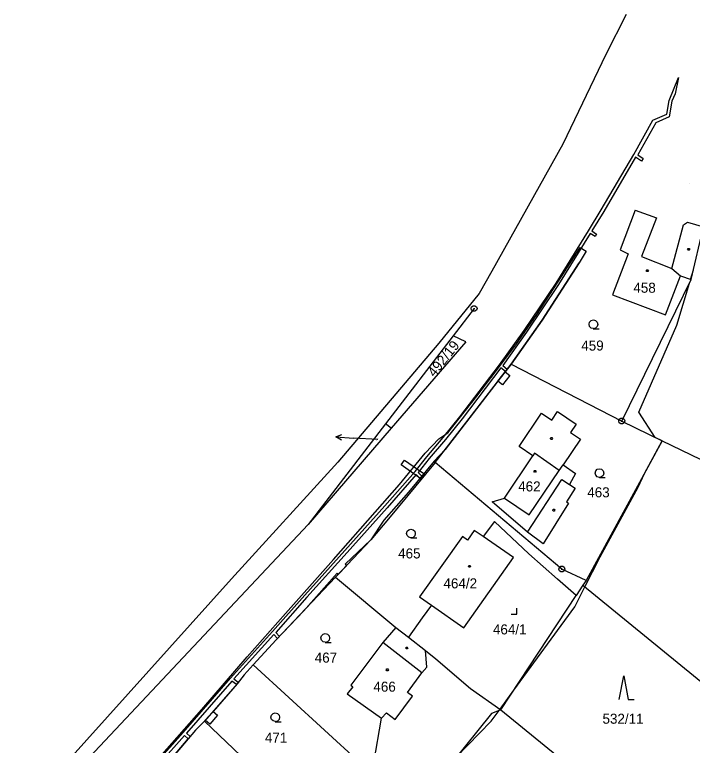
# Model space of a CAD drawing. Extents: x -759699 to -757730, y -1172308 to -1170857.
# Drawn here: x -759460.8 to -759346, y -1171711.2 to -1171587.4 of the extents above; entities that cross this region are included whole.
import ezdxf

# ---------------------------------------------------------------- set-up
doc = ezdxf.new("R2010")
doc.units = 0
for name, color, linetype in [('Vrstva 1', 7, 'Continuous'), ('Vrstva 11', 7, 'Continuous'), ('Vrstva 12', 7, 'Continuous'), ('Vrstva 13', 7, 'Continuous'), ('Vrstva 2', 7, 'Continuous'), ('Vrstva 3', 7, 'Continuous'), ('Vrstva 4', 7, 'Continuous'), ('Vrstva 5', 7, 'Continuous'), ('Vrstva 7', 7, 'Continuous'), ('Vrstva 8', 7, 'Continuous')]:
    doc.layers.add(name, color=color, linetype=linetype)

msp = doc.modelspace()

# ---------------------------------------------------------------- linework, layer by layer
at = {"layer": 'Vrstva 1'}
for p, q in [((-759355.74, -1171620.53), (-759358.28, -1171627.26)), ((-759355.74, -1171620.53), (-759355.74, -1171620.53)), ((-759346.22, -1171632.28), (-759344.12, -1171623.36)), ((-759356.89, -1171627.92), (-759359.55, -1171634.86)), ((-759358.28, -1171627.26), (-759356.89, -1171627.92)), ((-759371.45, -1171639.14), (-759365.18, -1171629.47)), ((-759365.18, -1171629.47), (-759365.18, -1171629.47)), ((-759350.56, -1171638.25), (-759348.04, -1171631.67)), ((-759348.04, -1171631.67), (-759346.22, -1171632.28)), ((-759357.99, -1171656.24), (-759346.22, -1171632.28)), ((-759359.55, -1171634.86), (-759350.56, -1171638.25)), ((-759382.99, -1171637.18), (-759386.53, -1171641.8)), ((-759382.99, -1171637.18), (-759382.99, -1171637.18)), ((-759376.73, -1171646.62), (-759371.45, -1171639.14)), ((-759386.53, -1171641.8), (-759397.96, -1171656.69)), ((-759384.4, -1171642.85), (-759397, -1171657.44)), ((-759384.4, -1171642.85), (-759386.53, -1171641.8)), ((-759384.4, -1171642.85), (-759384.4, -1171642.85)), ((-759389.58, -1171663.24), (-759376.73, -1171646.62)), ((-759376.73, -1171646.62), (-759357.99, -1171656.24)), ((-759375.36, -1171660.56), (-759371.57, -1171654.91)), ((-759371.57, -1171654.91), (-759369.84, -1171656.07)), ((-759369.84, -1171656.07), (-759368.88, -1171654.63)), ((-759368.88, -1171654.63), (-759365.71, -1171656.75)), ((-759357.99, -1171656.24), (-759351.15, -1171659.61)), ((-759397.96, -1171656.69), (-759411.06, -1171673.74)), ((-759397, -1171657.44), (-759411.06, -1171673.74)), ((-759397, -1171657.44), (-759397.96, -1171656.69)), ((-759365.71, -1171656.75), (-759366.68, -1171658.19)), ((-759366.68, -1171658.19), (-759364.99, -1171659.32)), ((-759364.99, -1171659.32), (-759367.9, -1171663.64)), ((-759351.15, -1171659.61), (-759364.03, -1171683.25)), ((-759351.15, -1171659.61), (-759313.61, -1171677.58)), ((-759373.03, -1171662.12), (-759375.36, -1171660.56)), ((-759377.85, -1171669.3), (-759373.03, -1171662.12)), ((-759389.58, -1171663.24), (-759397.5, -1171672.82)), ((-759368.13, -1171681.31), (-759389.58, -1171663.24)), ((-759367.9, -1171663.64), (-759365.84, -1171665.15)), ((-759365.84, -1171665.15), (-759366.86, -1171666.97)), ((-759365.9, -1171667.61), (-759367.36, -1171669.94)), ((-759366.86, -1171666.97), (-759365.9, -1171667.61)), ((-759379.9, -1171669.9), (-759377.85, -1171669.3)), ((-759373.97, -1171675.05), (-759379.9, -1171669.9)), ((-759366.98, -1171670.17), (-759371.29, -1171677.05)), ((-759367.36, -1171669.94), (-759366.98, -1171670.17)), ((-759411.06, -1171673.74), (-759460.06, -1171725.87)), ((-759397.5, -1171672.82), (-759400.48, -1171676.34)), ((-759379.51, -1171673.24), (-759381.45, -1171675.82)), ((-759373.71, -1171678.71), (-759379.51, -1171673.24)), ((-759382.98, -1171674.78), (-759384.11, -1171676.43)), ((-759381.45, -1171675.82), (-759382.98, -1171674.78)), ((-759371.29, -1171677.05), (-759373.97, -1171675.05)), ((-759400.48, -1171676.34), (-759406.46, -1171682.69)), ((-759384.94, -1171675.79), (-759392.24, -1171686.04)), ((-759384.11, -1171676.43), (-759384.94, -1171675.79)), ((-759376.3, -1171679.33), (-759381.45, -1171675.82)), ((-759368.84, -1171683.01), (-759373.71, -1171678.71)), ((-759384.72, -1171691.25), (-759376.3, -1171679.33)), ((-759364.03, -1171683.25), (-759368.13, -1171681.31)), ((-759406.46, -1171682.69), (-759416.48, -1171693.29)), ((-759406.46, -1171682.69), (-759396.24, -1171691.2)), ((-759365.7, -1171685.78), (-759368.84, -1171683.01)), ((-759364.03, -1171683.25), (-759364.55, -1171684.03)), ((-759364.55, -1171684.03), (-759365.7, -1171685.78)), ((-759364.55, -1171684.03), (-759333.09, -1171709.78)), ((-759392.24, -1171686.04), (-759390.2, -1171687.45)), ((-759378.43, -1171705.14), (-759365.7, -1171685.78)), ((-759390.2, -1171687.45), (-759391.8, -1171689.57)), ((-759390.2, -1171687.45), (-759384.72, -1171691.25)), ((-759391.8, -1171689.57), (-759394.11, -1171692.85)), ((-759396.24, -1171691.2), (-759398.45, -1171693.74)), ((-759396.24, -1171691.2), (-759394.11, -1171692.85)), ((-759416.48, -1171693.29), (-759420.41, -1171697.55)), ((-759398.45, -1171693.74), (-759403.86, -1171701)), ((-759394.11, -1171692.85), (-759391.21, -1171695.12)), ((-759391.21, -1171695.12), (-759389.44, -1171696.5)), ((-759389.44, -1171696.5), (-759383.58, -1171701.54)), ((-759420.41, -1171697.55), (-759421.89, -1171699.23)), ((-759420.41, -1171697.55), (-759400.3, -1171715.91)), ((-759421.89, -1171699.23), (-759423.12, -1171700.74)), ((-759423.12, -1171700.74), (-759428.63, -1171707.06)), ((-759403.86, -1171701), (-759403.53, -1171701.26)), ((-759403.53, -1171701.26), (-759404.46, -1171702.46)), ((-759383.58, -1171701.54), (-759378.43, -1171705.14)), ((-759404.46, -1171702.46), (-759398.64, -1171706.59)), ((-759380.05, -1171705.77), (-759393.97, -1171723.12)), ((-759378.43, -1171705.14), (-759380.05, -1171705.77)), ((-759378.43, -1171705.14), (-759347.86, -1171730.08)), ((-759428.63, -1171707.06), (-759430.17, -1171708.62)), ((-759428.63, -1171707.06), (-759414.89, -1171720.1)), ((-759400.3, -1171715.91), (-759398.64, -1171706.59)), ((-759430.17, -1171708.62), (-759431.38, -1171710.06)), ((-759436.98, -1171716.58), (-759431.38, -1171710.06))]:
    msp.add_line(p, q, dxfattribs=at)
at = {"layer": 'Vrstva 11'}
for p, q in [((-759357.23, -1171587.4), (-759360.66, -1171594.15)), ((-759360.66, -1171594.15), (-759367.98, -1171609.33)), ((-759367.98, -1171609.33), (-759379.99, -1171630.83)), ((-759379.99, -1171630.83), (-759382.14, -1171634.62)), ((-759346.32, -1171632.25), (-759345.84, -1171630.65)), ((-759348.67, -1171639.98), (-759346.51, -1171632.87)), ((-759346.51, -1171632.87), (-759346.22, -1171632.28)), ((-759346.22, -1171632.28), (-759346.32, -1171632.25)), ((-759382.14, -1171634.62), (-759388.98, -1171643.04)), ((-759355.12, -1171654.75), (-759348.67, -1171639.98)), ((-759388.98, -1171643.04), (-759406.08, -1171663.23)), ((-759352.31, -1171659.04), (-759355.12, -1171654.75)), ((-759351.15, -1171659.61), (-759352.31, -1171659.04)), ((-759354.14, -1171665.1), (-759351.15, -1171659.61)), ((-759406.08, -1171663.23), (-759424.03, -1171682.98)), ((-759355.21, -1171667.46), (-759354.14, -1171665.1)), ((-759361.65, -1171679.26), (-759355.21, -1171667.46)), ((-759364.22, -1171684.3), (-759361.65, -1171679.26)), ((-759424.03, -1171682.98), (-759460.77, -1171723.76)), ((-759365.95, -1171687.7), (-759364.22, -1171684.3)), ((-759376.24, -1171701.81), (-759365.95, -1171687.7)), ((-759378.59, -1171705.03), (-759376.24, -1171701.81)), ((-759380.07, -1171707.06), (-759378.76, -1171705.27)), ((-759378.76, -1171705.27), (-759378.59, -1171705.03)), ((-759386, -1171713.19), (-759380.07, -1171707.06))]:
    msp.add_line(p, q, dxfattribs=at)
at = {"layer": 'Vrstva 12'}
for p, q in [((-759355.74, -1171620.53), (-759358.28, -1171627.26)), ((-759355.74, -1171620.53), (-759352.08, -1171621.82)), ((-759352.08, -1171621.82), (-759354.66, -1171628.38)), ((-759356.89, -1171627.92), (-759359.55, -1171634.86)), ((-759358.28, -1171627.26), (-759356.89, -1171627.92)), ((-759354.66, -1171628.38), (-759349.48, -1171630.41)), ((-759349.48, -1171630.41), (-759348.04, -1171631.67)), ((-759350.56, -1171638.25), (-759348.04, -1171631.67)), ((-759359.55, -1171634.86), (-759350.56, -1171638.25)), ((-759377.85, -1171669.3), (-759373.03, -1171662.12)), ((-759372.77, -1171661.7), (-759373.03, -1171662.12)), ((-759368.57, -1171664.64), (-759372.77, -1171661.7)), ((-759373.67, -1171672.1), (-759368.57, -1171664.64)), ((-759377.85, -1171669.3), (-759373.67, -1171672.1)), ((-759382.98, -1171674.78), (-759384.11, -1171676.43)), ((-759381.45, -1171675.82), (-759382.98, -1171674.78)), ((-759384.94, -1171675.79), (-759392.24, -1171686.04)), ((-759384.11, -1171676.43), (-759384.94, -1171675.79)), ((-759376.3, -1171679.33), (-759381.45, -1171675.82)), ((-759384.72, -1171691.25), (-759376.3, -1171679.33)), ((-759392.24, -1171686.04), (-759390.2, -1171687.45)), ((-759390.2, -1171687.45), (-759384.72, -1171691.25)), ((-759398.45, -1171693.74), (-759403.86, -1171701)), ((-759391.82, -1171698.91), (-759398.45, -1171693.74)), ((-759394.23, -1171702.22), (-759391.82, -1171698.91)), ((-759403.86, -1171701), (-759403.53, -1171701.26)), ((-759403.53, -1171701.26), (-759404.46, -1171702.46)), ((-759393.41, -1171702.85), (-759394.23, -1171702.22)), ((-759404.46, -1171702.46), (-759398.64, -1171706.59)), ((-759396.37, -1171706.78), (-759393.41, -1171702.85)), ((-759398.64, -1171706.59), (-759397.8, -1171705.67)), ((-759397.8, -1171705.67), (-759396.37, -1171706.78))]:
    msp.add_line(p, q, dxfattribs=at)
at = {"layer": 'Vrstva 13'}
for p, q in [((-759349.97, -1171601.94), (-759348.4, -1171598.06)), ((-759348.4, -1171598.06), (-759348.97, -1171600.8)), ((-759348.97, -1171600.8), (-759349.49, -1171602.08)), ((-759350.37, -1171604.26), (-759349.97, -1171601.94)), ((-759349.49, -1171602.08), (-759349.94, -1171604.71)), ((-759352.7, -1171605.29), (-759350.37, -1171604.26)), ((-759355.96, -1171611.07), (-759352.7, -1171605.29)), ((-759352.21, -1171605.71), (-759355.29, -1171611.17)), ((-759349.94, -1171604.71), (-759352.21, -1171605.71)), ((-759361.46, -1171620.49), (-759355.96, -1171611.07)), ((-759355.65, -1171611.53), (-759361.03, -1171620.74)), ((-759354.63, -1171612.2), (-759355.65, -1171611.53)), ((-759355.29, -1171611.17), (-759354.37, -1171611.78)), ((-759354.37, -1171611.78), (-759354.63, -1171612.2)), ((-759363.61, -1171624), (-759361.46, -1171620.49)), ((-759361.03, -1171620.74), (-759363.05, -1171624.05)), ((-759369.1, -1171632.87), (-759363.61, -1171624)), ((-759363.05, -1171624.05), (-759362.25, -1171624.57)), ((-759363.31, -1171624.48), (-759368.68, -1171633.14)), ((-759362.5, -1171625), (-759363.31, -1171624.48)), ((-759362.25, -1171624.57), (-759362.5, -1171625)), ((-759368.8, -1171632.74), (-759365.01, -1171626.84)), ((-759365.01, -1171626.84), (-759364, -1171627.49)), ((-759364, -1171627.49), (-759365.18, -1171629.47)), ((-759365.18, -1171629.47), (-759371.45, -1171639.14)), ((-759374.53, -1171640.91), (-759369.1, -1171632.87)), ((-759372.36, -1171638.19), (-759368.8, -1171632.74)), ((-759368.68, -1171633.14), (-759374.12, -1171641.2)), ((-759371.45, -1171639.14), (-759376.73, -1171646.62)), ((-759375.94, -1171643.32), (-759372.36, -1171638.19)), ((-759378.68, -1171646.74), (-759374.53, -1171640.91)), ((-759374.12, -1171641.2), (-759378.14, -1171646.84)), ((-759379.41, -1171647.94), (-759375.94, -1171643.32)), ((-759376.73, -1171646.62), (-759377.71, -1171647.89)), ((-759385.4, -1171655.55), (-759378.68, -1171646.74)), ((-759378.44, -1171647.24), (-759385, -1171655.85)), ((-759382.54, -1171652.05), (-759379.41, -1171647.94)), ((-759377.71, -1171647.89), (-759378.94, -1171649.48)), ((-759378.94, -1171649.48), (-759377.71, -1171647.89)), ((-759377.67, -1171647.83), (-759378.44, -1171647.24)), ((-759378.14, -1171646.84), (-759377.36, -1171647.43)), ((-759377.71, -1171647.89), (-759376.92, -1171648.5)), ((-759377.36, -1171647.43), (-759377.67, -1171647.83)), ((-759376.92, -1171648.5), (-759378.15, -1171650.09)), ((-759378.94, -1171649.48), (-759387.89, -1171661.06)), ((-759378.15, -1171650.09), (-759378.94, -1171649.48)), ((-759387.41, -1171658.26), (-759382.54, -1171652.05)), ((-759388.21, -1171659.05), (-759385.4, -1171655.55)), ((-759385, -1171655.85), (-759387.82, -1171659.37)), ((-759390.96, -1171662.29), (-759388.21, -1171659.05)), ((-759388.93, -1171659.23), (-759387.41, -1171658.26)), ((-759391.27, -1171661.67), (-759388.93, -1171659.23)), ((-759387.82, -1171659.37), (-759390.57, -1171662.61)), ((-759387.89, -1171661.06), (-759389.77, -1171663.01)), ((-759395.62, -1171666.99), (-759391.27, -1171661.67)), ((-759392.97, -1171664.79), (-759390.96, -1171662.29)), ((-759390.57, -1171662.61), (-759392.44, -1171664.94)), ((-759395.34, -1171663.66), (-759394.76, -1171662.84)), ((-759392.39, -1171665.74), (-759395.34, -1171663.66)), ((-759394.76, -1171662.84), (-759391.85, -1171664.9)), ((-759389.77, -1171663.01), (-759394.11, -1171668.31)), ((-759398.1, -1171670.59), (-759392.97, -1171664.79)), ((-759392.44, -1171664.94), (-759391.66, -1171665.75)), ((-759391.25, -1171665.26), (-759391.89, -1171666.04)), ((-759391.85, -1171664.9), (-759391.25, -1171665.26)), ((-759392.77, -1171665.32), (-759397.72, -1171670.93)), ((-759391.98, -1171666.14), (-759392.77, -1171665.32)), ((-759391.89, -1171666.04), (-759392.39, -1171665.74)), ((-759391.66, -1171665.75), (-759391.98, -1171666.14)), ((-759399.75, -1171671.65), (-759395.62, -1171666.99)), ((-759394.11, -1171668.31), (-759398.29, -1171673.01)), ((-759404.84, -1171678.15), (-759398.1, -1171670.59)), ((-759397.72, -1171670.93), (-759404.47, -1171678.48)), ((-759406.78, -1171679.7), (-759399.75, -1171671.65)), ((-759398.29, -1171673.01), (-759400.48, -1171676.34)), ((-759400.48, -1171676.34), (-759404.79, -1171680.46)), ((-759411.66, -1171685.72), (-759404.84, -1171678.15)), ((-759404.47, -1171678.48), (-759411.28, -1171686.05)), ((-759414.9, -1171688.82), (-759406.78, -1171679.7)), ((-759404.61, -1171680.74), (-759406.02, -1171682.24)), ((-759404.79, -1171680.46), (-759404.61, -1171680.74)), ((-759406.17, -1171682.02), (-759411.89, -1171688.45)), ((-759406.02, -1171682.24), (-759406.17, -1171682.02)), ((-759417.09, -1171691.86), (-759411.66, -1171685.72)), ((-759411.28, -1171686.05), (-759416.57, -1171692.03)), ((-759411.89, -1171688.45), (-759416.48, -1171693.29)), ((-759421.41, -1171696.15), (-759414.9, -1171688.82)), ((-759424.23, -1171699.77), (-759417.09, -1171691.86)), ((-759416.9, -1171692.4), (-759423.67, -1171699.9)), ((-759416.28, -1171693.08), (-759416.9, -1171692.4)), ((-759416.57, -1171692.03), (-759415.94, -1171692.72)), ((-759416.48, -1171693.29), (-759420.41, -1171697.55)), ((-759415.94, -1171692.72), (-759416.28, -1171693.08)), ((-759429.1, -1171705.11), (-759421.41, -1171696.15)), ((-759420.41, -1171697.55), (-759421.89, -1171699.23)), ((-759432.23, -1171708.97), (-759424.23, -1171699.77)), ((-759423.67, -1171699.9), (-759422.9, -1171700.46)), ((-759421.89, -1171699.23), (-759423.12, -1171700.74)), ((-759424, -1171700.27), (-759431.68, -1171709.11)), ((-759423.12, -1171700.74), (-759427.18, -1171705.41)), ((-759423.22, -1171700.85), (-759424, -1171700.27)), ((-759422.9, -1171700.46), (-759423.22, -1171700.85)), ((-759437.42, -1171714.55), (-759429.1, -1171705.11)), ((-759428.5, -1171706.91), (-759427.18, -1171705.41)), ((-759427.18, -1171705.41), (-759428.5, -1171706.91)), ((-759426.43, -1171706.07), (-759427.74, -1171707.57)), ((-759427.18, -1171705.41), (-759426.43, -1171706.07)), ((-759428.63, -1171707.06), (-759430.17, -1171708.62)), ((-759428.5, -1171706.91), (-759428.63, -1171707.06)), ((-759428.49, -1171706.92), (-759428.5, -1171706.91)), ((-759427.74, -1171707.57), (-759428.49, -1171706.92)), ((-759441.11, -1171718.97), (-759432.23, -1171708.97)), ((-759432.02, -1171709.49), (-759440.58, -1171719.13)), ((-759431.38, -1171710.06), (-759432.02, -1171709.49)), ((-759431.68, -1171709.11), (-759431.03, -1171709.65)), ((-759430.17, -1171708.62), (-759431.38, -1171710.06)), ((-759431.03, -1171709.65), (-759431.38, -1171710.06)), ((-759431.38, -1171710.06), (-759436.98, -1171716.58))]:
    msp.add_line(p, q, dxfattribs=at)
at = {"layer": 'Vrstva 3'}
for points in [[(-759362.78, -1171640.59), (-759363.16, -1171640.49), (-759363.43, -1171640.22), (-759363.53, -1171639.85), (-759363.43, -1171639.48), (-759363.16, -1171639.21), (-759362.79, -1171639.11), (-759362.42, -1171639.21), (-759362.15, -1171639.48), (-759362.05, -1171639.86), (-759362.15, -1171640.24), (-759362.42, -1171640.51), (-759362.8, -1171640.61), (-759361.8, -1171640.61)], [(-759361.75, -1171665.79), (-759362.13, -1171665.69), (-759362.4, -1171665.42), (-759362.5, -1171665.05), (-759362.4, -1171664.68), (-759362.13, -1171664.41), (-759361.76, -1171664.31), (-759361.39, -1171664.41), (-759361.12, -1171664.68), (-759361.02, -1171665.06), (-759361.12, -1171665.44), (-759361.39, -1171665.71), (-759361.77, -1171665.81), (-759360.77, -1171665.81)], [(-759393.67, -1171676.02), (-759394.05, -1171675.92), (-759394.32, -1171675.65), (-759394.42, -1171675.28), (-759394.32, -1171674.91), (-759394.05, -1171674.64), (-759393.68, -1171674.54), (-759393.31, -1171674.64), (-759393.04, -1171674.91), (-759392.94, -1171675.29), (-759393.04, -1171675.67), (-759393.31, -1171675.94), (-759393.69, -1171676.04), (-759392.69, -1171676.04)], [(-759376.73, -1171688.94), (-759375.73, -1171688.94), (-759375.73, -1171687.94)], [(-759408.17, -1171693.72), (-759408.55, -1171693.62), (-759408.82, -1171693.35), (-759408.92, -1171692.98), (-759408.82, -1171692.61), (-759408.55, -1171692.34), (-759408.18, -1171692.24), (-759407.81, -1171692.34), (-759407.54, -1171692.61), (-759407.44, -1171692.99), (-759407.54, -1171693.37), (-759407.81, -1171693.64), (-759408.19, -1171693.74), (-759407.19, -1171693.74)], [(-759358.4, -1171703.39), (-759357.65, -1171699.39), (-759356.9, -1171703.39), (-759355.9, -1171703.39)], [(-759416.63, -1171707.14), (-759417.01, -1171707.04), (-759417.28, -1171706.77), (-759417.38, -1171706.4), (-759417.28, -1171706.03), (-759417.01, -1171705.76), (-759416.64, -1171705.66), (-759416.27, -1171705.76), (-759416, -1171706.03), (-759415.9, -1171706.41), (-759416, -1171706.79), (-759416.27, -1171707.06), (-759416.65, -1171707.16), (-759415.65, -1171707.16)]]:
    msp.add_lwpolyline(points, dxfattribs=at)
at = {"layer": 'Vrstva 4'}
for p, q in [((-759346.52, -1171615.96), (-759346.52, -1171615.96)), ((-759346.52, -1171615.96), (-759346.52, -1171615.96)), ((-759355.74, -1171620.53), (-759352.08, -1171621.82)), ((-759352.08, -1171621.82), (-759354.66, -1171628.38)), ((-759349.48, -1171630.41), (-759347.51, -1171622.98)), ((-759347.51, -1171622.98), (-759346.85, -1171622.58)), ((-759346.85, -1171622.58), (-759344.12, -1171623.36)), ((-759354.66, -1171628.38), (-759349.48, -1171630.41)), ((-759349.48, -1171630.41), (-759348.04, -1171631.67)), ((-759372.77, -1171661.7), (-759373.03, -1171662.12)), ((-759368.57, -1171664.64), (-759372.77, -1171661.7)), ((-759368.57, -1171664.64), (-759367.9, -1171663.64)), ((-759373.67, -1171672.1), (-759368.57, -1171664.64)), ((-759373.97, -1171675.05), (-759368.14, -1171666.12)), ((-759368.14, -1171666.12), (-759366.86, -1171666.97)), ((-759377.85, -1171669.3), (-759373.67, -1171672.1)), ((-759391.82, -1171698.91), (-759398.45, -1171693.74)), ((-759390.99, -1171697.92), (-759391.21, -1171695.12)), ((-759391.82, -1171698.91), (-759390.99, -1171697.92)), ((-759394.23, -1171702.22), (-759391.82, -1171698.91)), ((-759393.41, -1171702.85), (-759394.23, -1171702.22)), ((-759396.37, -1171706.78), (-759393.41, -1171702.85)), ((-759398.64, -1171706.59), (-759397.8, -1171705.67)), ((-759397.8, -1171705.67), (-759396.37, -1171706.78))]:
    msp.add_line(p, q, dxfattribs=at)
at = {"layer": 'Vrstva 5'}
for points in [[(-759346.56, -1171627.01), (-759346.47, -1171627.16), (-759346.56, -1171627.31), (-759346.74, -1171627.31), (-759346.83, -1171627.16), (-759346.74, -1171627.01)], [(-759353.57, -1171630.6), (-759353.48, -1171630.75), (-759353.57, -1171630.9), (-759353.75, -1171630.9), (-759353.84, -1171630.75), (-759353.75, -1171630.6)], [(-759369.8, -1171659.05), (-759369.71, -1171659.2), (-759369.8, -1171659.35), (-759369.98, -1171659.35), (-759370.07, -1171659.2), (-759369.98, -1171659.05)], [(-759372.59, -1171664.6), (-759372.5, -1171664.75), (-759372.59, -1171664.9), (-759372.77, -1171664.9), (-759372.86, -1171664.75), (-759372.77, -1171664.6)], [(-759369.41, -1171671.19), (-759369.32, -1171671.34), (-759369.41, -1171671.49), (-759369.59, -1171671.49), (-759369.68, -1171671.34), (-759369.59, -1171671.19)], [(-759383.67, -1171680.71), (-759383.58, -1171680.86), (-759383.67, -1171681.01), (-759383.85, -1171681.01), (-759383.94, -1171680.86), (-759383.85, -1171680.71)], [(-759394.29, -1171694.53), (-759394.2, -1171694.68), (-759394.29, -1171694.83), (-759394.47, -1171694.83), (-759394.56, -1171694.68), (-759394.47, -1171694.53)], [(-759397.58, -1171698.23), (-759397.49, -1171698.38), (-759397.58, -1171698.53), (-759397.76, -1171698.53), (-759397.85, -1171698.38), (-759397.76, -1171698.23)]]:
    msp.add_lwpolyline(points, close=True, dxfattribs=at)
at = {"layer": 'Vrstva 7'}
for p in [(-759406.384, -1171658.926), (-759399.3, -1171659.39)]:
    msp.add_line(p, (-759403.39, -1171659.12), dxfattribs=at)
msp.add_lwpolyline([(-759405.418, -1171659.489), (-759406.384, -1171658.926), (-759405.353, -1171658.492)], dxfattribs=at)
at = {"layer": 'Vrstva 8'}
for p, q in [((-759383.11, -1171637.18), (-759382.87, -1171637.18)), ((-759358.11, -1171656.24), (-759357.87, -1171656.24)), ((-759368.25, -1171681.31), (-759368.01, -1171681.31))]:
    msp.add_line(p, q, dxfattribs=at)
for points in [[(-759382.84, -1171636.7), (-759382.59, -1171636.88), (-759382.49, -1171637.17), (-759382.59, -1171637.46), (-759382.84, -1171637.64), (-759383.15, -1171637.64), (-759383.4, -1171637.46), (-759383.5, -1171637.17), (-759383.4, -1171636.88), (-759383.15, -1171636.7)], [(-759357.84, -1171655.76), (-759357.59, -1171655.94), (-759357.49, -1171656.23), (-759357.59, -1171656.52), (-759357.84, -1171656.7), (-759358.15, -1171656.7), (-759358.4, -1171656.52), (-759358.5, -1171656.23), (-759358.4, -1171655.94), (-759358.15, -1171655.76)], [(-759367.98, -1171680.83), (-759367.73, -1171681.01), (-759367.63, -1171681.3), (-759367.73, -1171681.59), (-759367.98, -1171681.77), (-759368.29, -1171681.77), (-759368.54, -1171681.59), (-759368.64, -1171681.3), (-759368.54, -1171681.01), (-759368.29, -1171680.83)]]:
    msp.add_lwpolyline(points, close=True, dxfattribs=at)

# ---------------------------------------------------------------- texts
at = {"layer": 'Vrstva 2'}
for s, p in [('458', (-759356.021, -1171634.51)), ('459', (-759364.841, -1171644.3)), ('462', (-759375.518, -1171668.16)), ('463', (-759363.821, -1171669.16)), ('465', (-759395.841, -1171679.51)), ('464/2', (-759388.167, -1171684.58)), ('464/1', (-759379.795, -1171692.38)), ('467', (-759409.964, -1171697.16)), ('466', (-759400.034, -1171702.08)), ('532/11', (-759361.244, -1171707.51)), ('471', (-759418.406, -1171710.73))]:
    msp.add_text(s, height=1.7, dxfattribs=at).set_placement(p)
for s, height, rotation, p in [('492/19', 1.7, 51.22243, (-759389.7, -1171648.9)), ('492/20', 0.1, 50.53488, (-759399.461, -1171659.585))]:
    msp.add_text(s, height=height, rotation=rotation, dxfattribs=at).set_placement(p)

doc.saveas('drawing.dxf')
